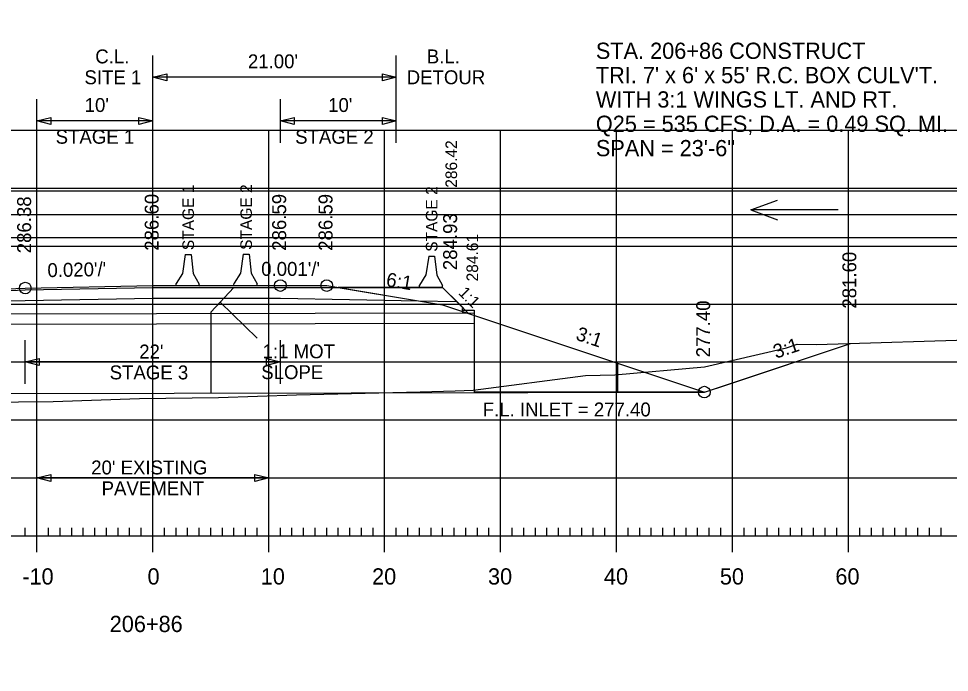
# Model space of a CAD drawing. Extents: x 1368713 to 1370673, y 380279 to 380950.
# Drawn here: x 1370498.1 to 1370578.3, y 380591 to 380647.4 of the extents above; entities that cross this region are included whole.
import ezdxf

# ---------------------------------------------------------------- set-up
doc = ezdxf.new("R2010")
doc.units = 0
for name, color, linetype in [('R_Alt Surface', 7, 'Continuous'), ('R_Axis', 7, 'Continuous'), ('R_Axis Annot', 7, 'Continuous'), ('R_Border Plan-Plan', 7, 'Continuous'), ('R_CONC BARRIER', 7, 'Continuous'), ('R_Detour', 7, 'Continuous'), ('R_Exist Surface', 7, 'Continuous'), ('R_Fin Surface', 7, 'Continuous'), ('R_Grid', 7, 'Continuous'), ('R_No Plot', 7, 'Continuous'), ('R_ROW Annot', 7, 'Continuous'), ('R_Stage 3 EW', 7, 'Continuous'), ('R_Water', 7, 'Continuous'), ('R_Water Annot', 7, 'Continuous'), ('R_Xsect Elev', 7, 'Continuous'), ('R_Xsect Slope', 7, 'Continuous')]:
    doc.layers.add(name, color=color, linetype=linetype)

msp = doc.modelspace()

# ---------------------------------------------------------------- linework, layer by layer
at = {"layer": 'R_Alt Surface'}
msp.add_line((1370532.546, 380623.026), (1370535.842, 380622.96), dxfattribs=at)
for points in [[(1370458.29, 380616.547), (1370460.529, 380615.8), (1370463.069, 380614.954), (1370484.629, 380622.14), (1370487.788, 380622.667), (1370494.629, 380623.807), (1370498.629, 380623.967), (1370509.629, 380624.187), (1370520.629, 380624.181), (1370534.629, 380624.174), (1370536.013, 380622.79), (1370536.871, 380621.932)], [(1370524.629, 380624.346), (1370534.629, 380622.679)], [(1370487.788, 380622.834), (1370498.629, 380623.05), (1370509.629, 380623.27), (1370520.629, 380623.265), (1370532.546, 380623.026)], [(1370534.629, 380622.679), (1370557.205, 380615.154)], [(1370557.205, 380615.154), (1370557.205, 380615.154), (1370569.813, 380619.356)]]:
    msp.add_lwpolyline(points, dxfattribs=at)
at = {"layer": 'R_Axis'}
for p, q in [((1370499.629, 380601.354), (1370499.629, 380604.154)), ((1370509.629, 380601.354), (1370509.629, 380604.154)), ((1370519.629, 380601.354), (1370519.629, 380604.154)), ((1370529.629, 380601.354), (1370529.629, 380604.154)), ((1370539.629, 380601.354), (1370539.629, 380604.154)), ((1370549.629, 380601.354), (1370549.629, 380604.154)), ((1370559.629, 380601.354), (1370559.629, 380604.154)), ((1370569.629, 380601.354), (1370569.629, 380604.154)), ((1370369.629, 380602.754), (1370649.629, 380602.754)), ((1370498.629, 380602.754), (1370498.629, 380603.454)), ((1370500.629, 380602.754), (1370500.629, 380603.454)), ((1370501.629, 380602.754), (1370501.629, 380603.454)), ((1370502.629, 380602.754), (1370502.629, 380603.454)), ((1370503.629, 380602.754), (1370503.629, 380603.454)), ((1370504.629, 380602.754), (1370504.629, 380603.454)), ((1370505.629, 380602.754), (1370505.629, 380603.454)), ((1370506.629, 380602.754), (1370506.629, 380603.454)), ((1370507.629, 380602.754), (1370507.629, 380603.454)), ((1370508.629, 380602.754), (1370508.629, 380603.454)), ((1370510.629, 380602.754), (1370510.629, 380603.454)), ((1370511.629, 380602.754), (1370511.629, 380603.454)), ((1370512.629, 380602.754), (1370512.629, 380603.454)), ((1370513.629, 380602.754), (1370513.629, 380603.454)), ((1370514.629, 380602.754), (1370514.629, 380603.454)), ((1370515.629, 380602.754), (1370515.629, 380603.454)), ((1370516.629, 380602.754), (1370516.629, 380603.454)), ((1370517.629, 380602.754), (1370517.629, 380603.454)), ((1370518.629, 380602.754), (1370518.629, 380603.454)), ((1370520.629, 380602.754), (1370520.629, 380603.454)), ((1370521.629, 380602.754), (1370521.629, 380603.454)), ((1370522.629, 380602.754), (1370522.629, 380603.454)), ((1370523.629, 380602.754), (1370523.629, 380603.454)), ((1370524.629, 380602.754), (1370524.629, 380603.454)), ((1370525.629, 380602.754), (1370525.629, 380603.454)), ((1370526.629, 380602.754), (1370526.629, 380603.454)), ((1370527.629, 380602.754), (1370527.629, 380603.454)), ((1370528.629, 380602.754), (1370528.629, 380603.454)), ((1370530.629, 380602.754), (1370530.629, 380603.454)), ((1370531.629, 380602.754), (1370531.629, 380603.454)), ((1370532.629, 380602.754), (1370532.629, 380603.454)), ((1370533.629, 380602.754), (1370533.629, 380603.454)), ((1370534.629, 380602.754), (1370534.629, 380603.454)), ((1370535.629, 380602.754), (1370535.629, 380603.454)), ((1370536.629, 380602.754), (1370536.629, 380603.454)), ((1370537.629, 380602.754), (1370537.629, 380603.454)), ((1370538.629, 380602.754), (1370538.629, 380603.454)), ((1370540.629, 380602.754), (1370540.629, 380603.454)), ((1370541.629, 380602.754), (1370541.629, 380603.454)), ((1370542.629, 380602.754), (1370542.629, 380603.454)), ((1370543.629, 380602.754), (1370543.629, 380603.454)), ((1370544.629, 380602.754), (1370544.629, 380603.454)), ((1370545.629, 380602.754), (1370545.629, 380603.454)), ((1370546.629, 380602.754), (1370546.629, 380603.454)), ((1370547.629, 380602.754), (1370547.629, 380603.454)), ((1370548.629, 380602.754), (1370548.629, 380603.454)), ((1370550.629, 380602.754), (1370550.629, 380603.454)), ((1370551.629, 380602.754), (1370551.629, 380603.454)), ((1370552.629, 380602.754), (1370552.629, 380603.454)), ((1370553.629, 380602.754), (1370553.629, 380603.454)), ((1370554.629, 380602.754), (1370554.629, 380603.454)), ((1370555.629, 380602.754), (1370555.629, 380603.454)), ((1370556.629, 380602.754), (1370556.629, 380603.454)), ((1370557.629, 380602.754), (1370557.629, 380603.454)), ((1370558.629, 380602.754), (1370558.629, 380603.454)), ((1370560.629, 380602.754), (1370560.629, 380603.454)), ((1370561.629, 380602.754), (1370561.629, 380603.454)), ((1370562.629, 380602.754), (1370562.629, 380603.454)), ((1370563.629, 380602.754), (1370563.629, 380603.454)), ((1370564.629, 380602.754), (1370564.629, 380603.454)), ((1370565.629, 380602.754), (1370565.629, 380603.454)), ((1370566.629, 380602.754), (1370566.629, 380603.454)), ((1370567.629, 380602.754), (1370567.629, 380603.454)), ((1370568.629, 380602.754), (1370568.629, 380603.454)), ((1370570.629, 380602.754), (1370570.629, 380603.454)), ((1370571.629, 380602.754), (1370571.629, 380603.454)), ((1370572.629, 380602.754), (1370572.629, 380603.454)), ((1370573.629, 380602.754), (1370573.629, 380603.454)), ((1370574.629, 380602.754), (1370574.629, 380603.454)), ((1370575.629, 380602.754), (1370575.629, 380603.454)), ((1370576.629, 380602.754), (1370576.629, 380603.454)), ((1370577.629, 380602.754), (1370577.629, 380603.454))]:
    msp.add_line(p, q, dxfattribs=at)
at = {"layer": 'R_Border Plan-Plan'}
msp.add_line((1370351.629, 380630.484), (1370667.809, 380630.484), dxfattribs=at)
at = {"layer": 'R_CONC BARRIER'}
for p, q in [((1370512.433, 380627.037), (1370512.933, 380627.027)), ((1370517.433, 380627.065), (1370517.933, 380627.055)), ((1370533.433, 380626.898), (1370533.933, 380626.888)), ((1370511.629, 380624.353), (1370511.632, 380624.519)), ((1370513.629, 380624.313), (1370513.632, 380624.479)), ((1370516.629, 380624.38), (1370516.633, 380624.547)), ((1370516.629, 380624.38), (1370518.629, 380624.34)), ((1370518.629, 380624.34), (1370518.632, 380624.507)), ((1370532.629, 380624.214), (1370532.633, 380624.38)), ((1370511.629, 380624.353), (1370513.629, 380624.313)), ((1370532.629, 380624.214), (1370534.629, 380624.174)), ((1370534.629, 380624.174), (1370534.632, 380624.34))]:
    msp.add_line(p, q, dxfattribs=at)
for points in [[(1370512.433, 380627.037), (1370512.181, 380625.399), (1370511.632, 380624.519)], [(1370512.933, 380627.027), (1370513.119, 380625.38), (1370513.632, 380624.479)], [(1370517.433, 380627.065), (1370517.182, 380625.427), (1370516.633, 380624.547)], [(1370517.933, 380627.055), (1370518.119, 380625.408), (1370518.632, 380624.507)], [(1370533.433, 380626.898), (1370533.182, 380625.26), (1370532.633, 380624.38)], [(1370533.933, 380626.888), (1370534.119, 380625.241), (1370534.632, 380624.34)]]:
    msp.add_lwpolyline(points, dxfattribs=at)
at = {"layer": 'R_Detour'}
for p, q in [((1370516.629, 380624.183), (1370514.629, 380622.064)), ((1370518.618, 380619.812), (1370515.437, 380622.92)), ((1370514.629, 380622.064), (1370514.629, 380615.064))]:
    msp.add_line(p, q, dxfattribs=at)
at = {"layer": 'R_Exist Surface'}
msp.add_lwpolyline([(1370449.471, 380617.403), (1370451.791, 380617.165), (1370452.425, 380617.112), (1370457.079, 380616.657), (1370469.439, 380615.53), (1370473.446, 380615.059), (1370485.06, 380614.515), (1370488.22, 380614.645), (1370495.03, 380614.288), (1370501.02, 380614.356), (1370508.483, 380614.618), (1370515.291, 380614.679), (1370522.013, 380614.914), (1370532.683, 380615.192), (1370535.712, 380615.264), (1370537.263, 380615.311), (1370546.951, 380616.579), (1370549.486, 380616.657), (1370557.212, 380617.332), (1370564.303, 380618.98), (1370565.209, 380619.298), (1370566.886, 380619.265), (1370581.754, 380619.728)], dxfattribs=at)
at = {"layer": 'R_Fin Surface'}
for points in [[(1370457.601, 380616.61), (1370459.863, 380615.856), (1370462.569, 380614.954), (1370484.629, 380622.307), (1370487.788, 380622.834), (1370494.629, 380623.974), (1370498.629, 380624.134), (1370509.629, 380624.354), (1370520.629, 380624.348), (1370524.629, 380624.346), (1370532.546, 380623.026), (1370534.629, 380622.679), (1370557.205, 380615.154), (1370559.218, 380615.825), (1370569.813, 380619.356)], [(1370494.629, 380623.974), (1370498.629, 380624.134), (1370509.629, 380624.354), (1370520.629, 380624.348), (1370524.629, 380624.346)]]:
    msp.add_lwpolyline(points, dxfattribs=at)
at = {"layer": 'R_Grid'}
for p, q in [((1370369.629, 380637.754), (1370649.629, 380637.754)), ((1370499.629, 380602.754), (1370499.629, 380637.754)), ((1370509.629, 380602.754), (1370509.629, 380637.754)), ((1370519.629, 380602.754), (1370519.629, 380637.754)), ((1370529.629, 380602.754), (1370529.629, 380637.754)), ((1370539.629, 380602.754), (1370539.629, 380637.754)), ((1370549.629, 380602.754), (1370549.629, 380637.754)), ((1370559.629, 380602.754), (1370559.629, 380637.754)), ((1370569.629, 380602.754), (1370569.629, 380637.754)), ((1370369.629, 380632.754), (1370649.629, 380632.754)), ((1370369.629, 380627.754), (1370649.629, 380627.754)), ((1370369.629, 380622.754), (1370649.629, 380622.754)), ((1370369.629, 380617.754), (1370649.629, 380617.754)), ((1370369.629, 380612.754), (1370649.629, 380612.754)), ((1370369.629, 380607.754), (1370649.629, 380607.754)), ((1370369.629, 380602.754), (1370649.629, 380602.754))]:
    msp.add_line(p, q, dxfattribs=at)
at = {"layer": 'R_No Plot'}
for points in [[(1370665.809, 380632.484), (1370353.629, 380632.484), (1370353.629, 380731.214), (1370603.169, 380731.214), (1370603.169, 380721.334), (1370620.709, 380721.334), (1370644.809, 380721.334), (1370644.809, 380699.001), (1370665.809, 380699.001)], [(1370353.629, 380628.484), (1370665.809, 380628.484), (1370665.809, 380529.754), (1370353.629, 380529.754)]]:
    msp.add_lwpolyline(points, close=True, dxfattribs=at)
for centre in [(1370498.629, 380624.134), (1370498.629, 380624.134), (1370520.629, 380624.348), (1370520.629, 380624.348), (1370524.629, 380624.346), (1370524.629, 380624.346), (1370557.205, 380615.154), (1370557.205, 380615.154)]:
    msp.add_circle(centre, 0.5, dxfattribs=at)
at = {"layer": 'R_ROW Annot'}
for p, q in [((1370509.629, 380640.439), (1370509.629, 380644.207)), ((1370530.629, 380640.439), (1370530.629, 380644.207)), ((1370530.629, 380642.323), (1370509.629, 380642.323)), ((1370499.629, 380636.67), (1370499.629, 380640.439)), ((1370509.629, 380636.67), (1370509.629, 380640.439)), ((1370520.629, 380636.67), (1370520.629, 380640.439)), ((1370530.629, 380636.67), (1370530.629, 380640.439)), ((1370509.629, 380638.555), (1370499.629, 380638.555)), ((1370530.629, 380638.555), (1370520.629, 380638.555)), ((1370498.629, 380615.869), (1370498.629, 380619.638)), ((1370520.629, 380615.869), (1370520.629, 380619.638)), ((1370520.629, 380617.754), (1370498.629, 380617.754)), ((1370499.629, 380605.869), (1370499.629, 380609.638)), ((1370519.629, 380605.869), (1370519.629, 380609.638)), ((1370519.629, 380607.754), (1370499.629, 380607.754))]:
    msp.add_line(p, q, dxfattribs=at)
for points in [[(1370510.829, 380642.023), (1370509.629, 380642.323), (1370510.829, 380642.623)], [(1370529.429, 380642.623), (1370530.629, 380642.323), (1370529.429, 380642.023)], [(1370500.829, 380638.255), (1370499.629, 380638.555), (1370500.829, 380638.855)], [(1370508.429, 380638.855), (1370509.629, 380638.555), (1370508.429, 380638.255)], [(1370521.829, 380638.255), (1370520.629, 380638.555), (1370521.829, 380638.855)], [(1370529.429, 380638.855), (1370530.629, 380638.555), (1370529.429, 380638.255)], [(1370499.829, 380617.454), (1370498.629, 380617.754), (1370499.829, 380618.054)], [(1370519.429, 380618.054), (1370520.629, 380617.754), (1370519.429, 380617.454)], [(1370500.829, 380607.454), (1370499.629, 380607.754), (1370500.829, 380608.054)], [(1370518.429, 380608.054), (1370519.629, 380607.754), (1370518.429, 380607.454)]]:
    msp.add_lwpolyline(points, close=True, dxfattribs=at)
at = {"layer": 'R_Stage 3 EW'}
for p, q in [((1370534.629, 380624.174), (1370525.632, 380624.178)), ((1370525.632, 380624.178), (1370532.546, 380623.026)), ((1370536.443, 380622.36), (1370534.629, 380624.174)), ((1370532.546, 380623.026), (1370534.629, 380622.679)), ((1370534.629, 380622.679), (1370536.337, 380622.11)), ((1370536.337, 380622.11), (1370536.337, 380622.36)), ((1370536.337, 380622.36), (1370536.443, 380622.36))]:
    msp.add_line(p, q, dxfattribs=at)
at = {"layer": 'R_Water'}
for p, q in [((1370482.701, 380621.871), (1370537.336, 380621.987)), ((1370536.337, 380622.235), (1370536.337, 380621.985)), ((1370536.337, 380622.235), (1370537.337, 380622.235)), ((1370537.337, 380622.235), (1370537.337, 380615.11)), ((1370482.703, 380620.996), (1370537.337, 380621.112)), ((1370549.752, 380615.138), (1370549.752, 380617.638)), ((1370462.569, 380614.954), (1370557.205, 380615.154)), ((1370557.205, 380615.154), (1370537.337, 380615.154))]:
    msp.add_line(p, q, dxfattribs=at)
at = {"layer": 'R_Water Annot'}
for p, q in [((1370561.208, 380630.869), (1370563.516, 380631.709)), ((1370568.749, 380630.869), (1370561.208, 380630.869)), ((1370561.208, 380630.869), (1370563.516, 380630.029))]:
    msp.add_line(p, q, dxfattribs=at)

# ---------------------------------------------------------------- texts
at = {"layer": 'R_Axis Annot'}
for s, p in [('STA. 206+86 CONSTRUCT', (1370547.847, 380643.906)), ("TRI. 7' x 6' x 55' R.C. BOX CULV'T.", (1370547.847, 380641.806)), ('WITH 3:1 WINGS LT. AND RT.', (1370547.847, 380639.706)), ('Q25 = 535 CFS; D.A. = 0.49 SQ. MI.', (1370547.847, 380637.606)), ('SPAN = 23\'-6"', (1370547.847, 380635.506)), ('-10', (1370498.367, 380598.554)), ('0', (1370509.172, 380598.554)), ('10', (1370518.94, 380598.554)), ('20', (1370528.543, 380598.554)), ('30', (1370538.543, 380598.554)), ('40', (1370548.543, 380598.554)), ('50', (1370558.543, 380598.554)), ('60', (1370568.51, 380598.554)), ('206+86', (1370505.909, 380594.454))]:
    msp.add_text(s, height=1.4, dxfattribs=at).set_placement(p)
at = {"layer": 'R_CONC BARRIER'}
for s, p in [(' STAGE 1', (1370513.183, 380627.032)), (' STAGE 2', (1370518.183, 380627.06)), (' STAGE 2', (1370534.183, 380626.893))]:
    msp.add_text(s, height=1, rotation=90, dxfattribs=at).set_placement(p)
at = {"layer": 'R_Detour'}
for s, p in [('1:1 MOT', (1370519.1, 380618.076)), ('SLOPE', (1370518.982, 380616.276))]:
    msp.add_text(s, height=1.2, dxfattribs=at).set_placement(p)
at = {"layer": 'R_ROW Annot'}
for s, p in [('C.L.', (1370504.665, 380643.519)), ('B.L.', (1370533.265, 380643.519)), ("21.00'", (1370517.833, 380643.093)), ('SITE 1', (1370503.73, 380641.719)), ('DETOUR', (1370531.531, 380641.719)), ("10'", (1370503.75, 380639.324)), ("10'", (1370524.75, 380639.324)), ('STAGE 1', (1370501.246, 380636.585)), ('STAGE 2', (1370521.906, 380636.585)), ("22'", (1370508.457, 380618.054)), ('STAGE 3', (1370505.906, 380616.254)), ("20' EXISTING", (1370504.314, 380608.054)), ('PAVEMENT', (1370505.212, 380606.254))]:
    msp.add_text(s, height=1.2, dxfattribs=at).set_placement(p)
at = {"layer": 'R_Xsect Elev'}
for s, height, p in [('286.42', 1, (1370535.876, 380632.788)), ('286.38', 1.2, (1370499.129, 380627.134)), ('286.60', 1.2, (1370510.129, 380627.354)), ('286.59', 1.2, (1370521.129, 380627.348)), ('286.59', 1.2, (1370525.129, 380627.346)), ('284.93', 1.2, (1370535.876, 380625.679)), ('284.61', 1, (1370537.69, 380624.709)), ('281.60', 1.2, (1370570.313, 380622.356)), ('277.40', 1.2, (1370557.705, 380618.154))]:
    msp.add_text(s, height=height, rotation=90, dxfattribs=at).set_placement(p)
at = {"layer": 'R_Xsect Slope'}
for s, height, rotation, p in [("0.020'/'", 1.2, 1.14576, (1370500.549, 380625.072)), ("0.001'/'", 1.2, 359.96966, (1370518.978, 380625.186)), ('6:1', 1.2, 350.53766, (1370529.695, 380624.307)), ('1:1', 1, 315, (1370535.935, 380623.659)), ('3:1', 1.2, 341.56507, (1370546.044, 380619.696)), ('3:1', 1.2, 18.43493, (1370563.382, 380618.034)), ('F.L. INLET = 277.40', 1.2, 360, (1370538.088, 380613.058))]:
    msp.add_text(s, height=height, rotation=rotation, dxfattribs=at).set_placement(p)

doc.saveas('drawing.dxf')
